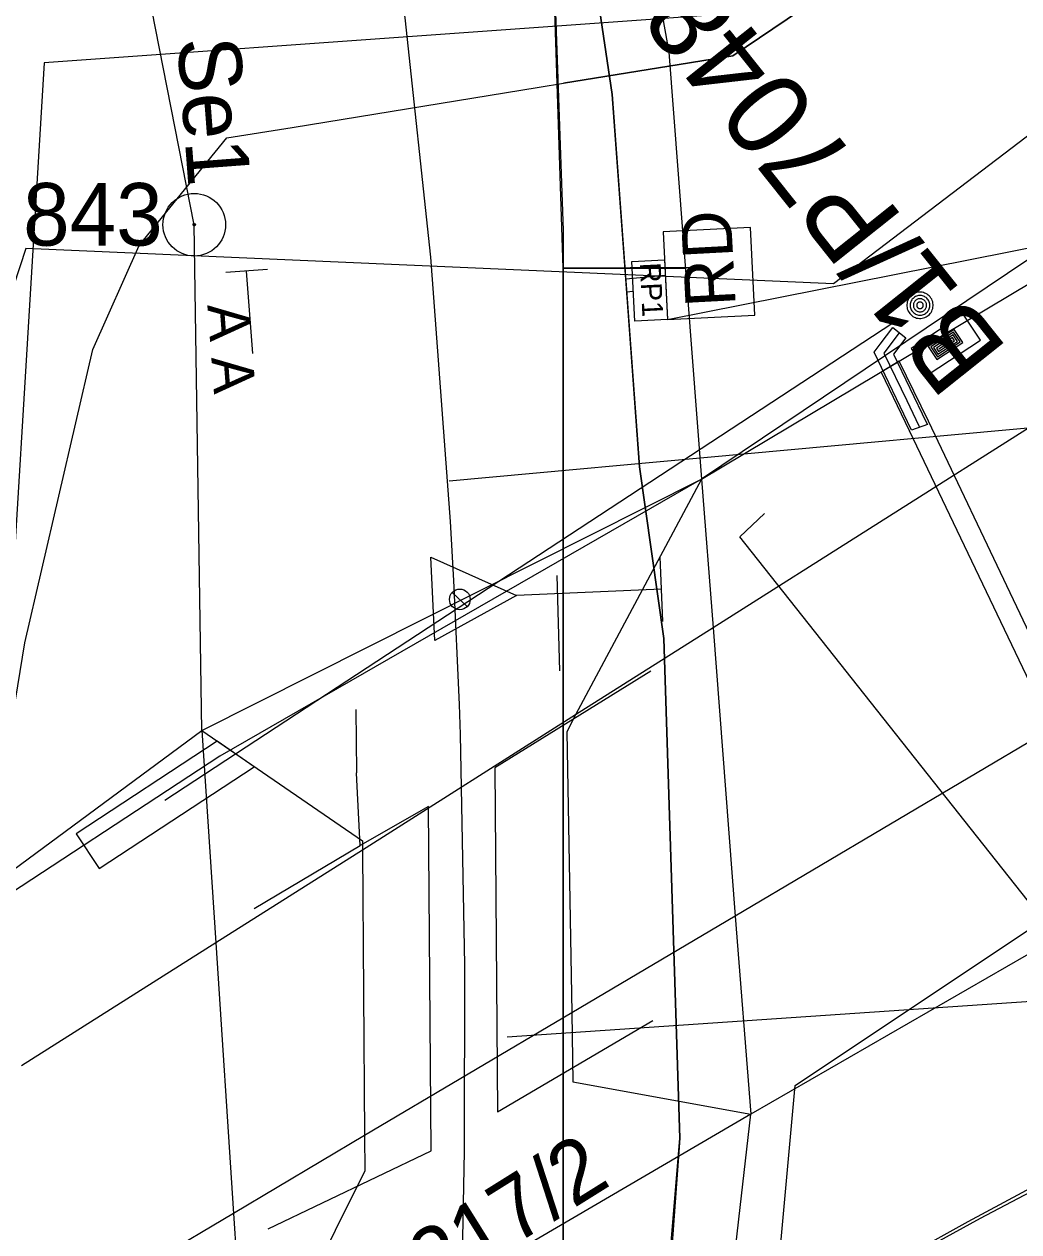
# Model space of a CAD drawing. Extents: x -620475 to -619963, y -1123010 to -1122510.
# Drawn here: x -620144.64 to -620120.79, y -1122910.94 to -1122881.99 of the extents above; entities that cross this region are included whole.
import ezdxf

# ---------------------------------------------------------------- set-up
doc = ezdxf.new("R2010")
doc.units = 0
for name, color, linetype in [('060603_ROZVODY_NN', 7, 'Continuous'), ('bubliny', 7, 'Continuous'), ('CD-T  SDK', 7, 'Continuous'), ('CETIN', 7, 'Continuous'), ('EON-nadzemní NN', 7, 'Continuous'), ('EON-podzemní NN', 7, 'Continuous'), ('HranDP', 7, 'Continuous'), ('Hranice parcel', 7, 'Continuous'), ('Město Bystřice-osvětlení', 7, 'Continuous'), ('Parcelní čísla', 7, 'Continuous'), ('PS 06-14-01_trasa_sdělovací_nové', 7, 'Continuous'), ('SSZT', 7, 'Continuous'), ('SSZT-DK', 7, 'Continuous'), ('SSZT-DK SDK', 7, 'Continuous'), ('SSZT-TK', 7, 'Continuous'), ('VAS el kabel', 7, 'Continuous'), ('Vnitřní kresba', 7, 'Continuous'), ('Vrstva 1', 7, 'Continuous'), ('Vrstva 19', 7, 'Continuous'), ('Vrstva 2', 7, 'Continuous'), ('Vrstva 3', 7, 'Continuous'), ('Vrstva 4', 7, 'Continuous'), ('Vrstva 51', 7, 'Continuous'), ('Vrstva 6', 7, 'Continuous'), ('Vrstva 8', 7, 'Continuous'), ('Věcná břemena k části', 7, 'Continuous'), ('Značky bodu BP', 7, 'Continuous'), ('ČD-T', 7, 'Continuous')]:
    doc.layers.add(name, color=color, linetype=linetype)

# ---------------------------------------------------------------- blocks, each defined once
blk = doc.blocks.new('NN460')
at = {"layer": 'Vrstva 2'}
for points in [[(0.628, 0), (0.624, 0.066), (0.614, 0.132), (0.597, 0.195), (0.573, 0.257), (0.543, 0.315), (0.507, 0.371), (0.466, 0.422), (0.419, 0.468), (0.368, 0.51), (0.312, 0.546), (0.254, 0.576), (0.192, 0.6), (0.129, 0.617), (0.063, 0.627), (-0.003, 0.631), (-0.068, 0.627), (-0.133, 0.617), (-0.197, 0.6), (-0.259, 0.576), (-0.317, 0.546), (-0.373, 0.51), (-0.424, 0.468), (-0.471, 0.422), (-0.512, 0.371), (-0.548, 0.315), (-0.578, 0.257), (-0.602, 0.195), (-0.619, 0.132), (-0.629, 0.066), (-0.632, 0), (-0.629, -0.065), (-0.619, -0.131), (-0.602, -0.194), (-0.578, -0.256), (-0.548, -0.315), (-0.512, -0.37), (-0.471, -0.421), (-0.424, -0.468), (-0.373, -0.509), (-0.317, -0.545), (-0.259, -0.575), (-0.197, -0.599), (-0.133, -0.616), (-0.068, -0.626), (-0.003, -0.63), (0.063, -0.626), (0.129, -0.616), (0.192, -0.599), (0.254, -0.575), (0.313, -0.545), (0.368, -0.509), (0.419, -0.468), (0.466, -0.421), (0.507, -0.37), (0.543, -0.315), (0.573, -0.256), (0.597, -0.194), (0.614, -0.131), (0.624, -0.065), (0.628, 0)], [(0.47, 0), (0.467, 0.05), (0.46, 0.099), (0.447, 0.147), (0.429, 0.193), (0.407, 0.237), (0.38, 0.278), (0.349, 0.317), (0.314, 0.352), (0.275, 0.383), (0.234, 0.41), (0.19, 0.432), (0.144, 0.45), (0.096, 0.463), (0.047, 0.47), (-0.003, 0.473), (-0.052, 0.47), (-0.1, 0.463), (-0.148, 0.45), (-0.194, 0.432), (-0.239, 0.41), (-0.28, 0.383), (-0.319, 0.352), (-0.353, 0.317), (-0.385, 0.278), (-0.411, 0.237), (-0.434, 0.193), (-0.452, 0.147), (-0.465, 0.099), (-0.472, 0.05), (-0.475, 0), (-0.472, -0.049), (-0.465, -0.098), (-0.452, -0.146), (-0.434, -0.192), (-0.411, -0.236), (-0.385, -0.277), (-0.353, -0.316), (-0.318, -0.351), (-0.28, -0.382), (-0.239, -0.409), (-0.194, -0.431), (-0.148, -0.449), (-0.1, -0.462), (-0.052, -0.469), (-0.003, -0.472), (0.047, -0.469), (0.096, -0.462), (0.144, -0.449), (0.19, -0.431), (0.234, -0.409), (0.275, -0.382), (0.314, -0.351), (0.349, -0.316), (0.38, -0.277), (0.407, -0.236), (0.429, -0.192), (0.447, -0.146), (0.46, -0.098), (0.467, -0.049), (0.47, 0)], [(0.313, 0), (0.311, 0.033), (0.306, 0.066), (0.297, 0.098), (0.285, 0.129), (0.27, 0.158), (0.252, 0.186), (0.232, 0.211), (0.208, 0.234), (0.183, 0.255), (0.155, 0.273), (0.126, 0.288), (0.095, 0.3), (0.063, 0.309), (0.03, 0.314), (-0.003, 0.315), (-0.035, 0.314), (-0.068, 0.309), (-0.1, 0.3), (-0.13, 0.288), (-0.16, 0.273), (-0.187, 0.255), (-0.213, 0.234), (-0.237, 0.211), (-0.257, 0.186), (-0.275, 0.158), (-0.29, 0.129), (-0.302, 0.098), (-0.31, 0.066), (-0.316, 0.033), (-0.317, 0), (-0.316, -0.033), (-0.31, -0.065), (-0.302, -0.097), (-0.29, -0.128), (-0.275, -0.157), (-0.257, -0.185), (-0.237, -0.21), (-0.213, -0.234), (-0.187, -0.254), (-0.16, -0.272), (-0.13, -0.287), (-0.1, -0.299), (-0.068, -0.308), (-0.035, -0.313), (-0.003, -0.315), (0.03, -0.313), (0.063, -0.308), (0.095, -0.299), (0.126, -0.287), (0.155, -0.272), (0.183, -0.254), (0.208, -0.234), (0.232, -0.21), (0.252, -0.185), (0.27, -0.157), (0.285, -0.128), (0.297, -0.097), (0.306, -0.065), (0.311, -0.032), (0.313, 0)], [(0.155, 0), (0.154, 0.017), (0.152, 0.033), (0.147, 0.049), (0.142, 0.064), (0.134, 0.079), (0.125, 0.093), (0.115, 0.106), (0.103, 0.118), (0.09, 0.128), (0.076, 0.137), (0.062, 0.144), (0.046, 0.15), (0.03, 0.154), (0.014, 0.157), (-0.003, 0.158), (-0.019, 0.157), (-0.035, 0.154), (-0.051, 0.15), (-0.066, 0.144), (-0.081, 0.137), (-0.095, 0.128), (-0.108, 0.118), (-0.119, 0.106), (-0.13, 0.093), (-0.139, 0.079), (-0.146, 0.064), (-0.152, 0.049), (-0.156, 0.033), (-0.159, 0.017), (-0.16, 0), (-0.159, -0.016), (-0.156, -0.032), (-0.152, -0.048), (-0.146, -0.064), (-0.139, -0.078), (-0.13, -0.092), (-0.119, -0.105), (-0.108, -0.117), (-0.095, -0.127), (-0.081, -0.136), (-0.066, -0.143), (-0.051, -0.149), (-0.035, -0.153), (-0.019, -0.156), (-0.003, -0.157), (0.014, -0.156), (0.03, -0.153), (0.046, -0.149), (0.062, -0.143), (0.076, -0.136), (0.09, -0.127), (0.103, -0.117), (0.115, -0.105), (0.125, -0.092), (0.134, -0.078), (0.142, -0.064), (0.147, -0.048), (0.152, -0.032), (0.154, -0.016), (0.155, 0)]]:
    blk.add_lwpolyline(points, dxfattribs=at)
blk = doc.blocks.new('NN620')
at = {"layer": 'Vrstva 8'}
for points in [[(0.752, 0.004), (-0.748, 0.004)], [(-0.748, 0.004), (-0.748, -0.746)], [(0.752, -0.746), (0.752, 0.004)], [(0.368, -0.18), (-0.376, -0.18)], [(-0.376, -0.18), (-0.376, -0.558)], [(0.321, -0.227), (-0.329, -0.227)], [(-0.329, -0.227), (-0.329, -0.51)], [(0.274, -0.274), (-0.281, -0.274)], [(-0.281, -0.274), (-0.281, -0.463)], [(0.274, -0.463), (0.274, -0.274)], [(0.321, -0.51), (0.321, -0.227)], [(0.368, -0.558), (0.368, -0.18)], [(-0.376, -0.558), (0.368, -0.558)], [(-0.329, -0.51), (0.321, -0.51)], [(-0.281, -0.463), (0.274, -0.463)], [(0.227, -0.321), (-0.234, -0.321)], [(-0.234, -0.321), (-0.234, -0.416)], [(-0.234, -0.416), (0.227, -0.416)], [(-0.193, -0.369), (0.185, -0.369)], [(0.227, -0.416), (0.227, -0.321)], [(-0.748, -0.746), (0.752, -0.746)]]:
    blk.add_lwpolyline(points, dxfattribs=at)

msp = doc.modelspace()

# ---------------------------------------------------------------- linework, layer by layer
at = {"layer": '060603_ROZVODY_NN'}
msp.add_lwpolyline([(-620240.174, -1122718.342), (-620228.339, -1122728.069), (-620221.166, -1122735.76), (-620213.633, -1122742.038), (-620205.954, -1122748.188), (-620177.512, -1122774.524), (-620185.522, -1122781.049), (-620181.59, -1122785.57), (-620173.131, -1122796.401), (-620158.909, -1122820.61), (-620151.64, -1122838.53), (-620148.846, -1122845.743), (-620146.967, -1122851.788), (-620142.651, -1122873.562), (-620132.315, -1122871.722), (-620130.544, -1122883.681), (-620130.195, -1122888.406), (-620130.037, -1122888.394)], dxfattribs=at)
msp.add_lwpolyline([(-620129.287, -1122887.643), (-620129.216, -1122889.068), (-620130.001, -1122889.107), (-620130.072, -1122887.682)], close=True, dxfattribs=at)
at = {"layer": 'bubliny'}
msp.add_line((-620129.216, -1122889.068), (-620082.81, -1122879.869), dxfattribs=at)
at = {"layer": 'CD-T  SDK'}
msp.add_lwpolyline([(-620105.449, -1122868.581), (-620124.482, -1122881.511), (-620144.155, -1122882.921), (-620145.292, -1122901.532), (-620189.847, -1122929.066)], dxfattribs=at)
at = {"layer": 'CETIN'}
for points in [[(-620127.251, -1122919.476), (-620126.15, -1122907.427), (-620051.64, -1122857.73)], [(-620170.67, -1122919.52), (-620165.17, -1122915.89), (-620159.81, -1122912.93), (-620154.47, -1122909.86), (-620149, -1122906.77), (-620145.47, -1122904.13), (-620145.58, -1122902.66), (-620144.62, -1122896.82), (-620142.99, -1122889.79), (-620141.88, -1122887.3), (-620139.78, -1122884.72), (-620138.21, -1122884.47), (-620132.29, -1122883.5), (-620131.71, -1122883.41), (-620127.65, -1122882.75), (-620121.18, -1122878.38), (-620115.35, -1122873.32), (-620112.07, -1122871.4), (-620109.58, -1122869.93), (-620106.94, -1122868.3), (-620100.13, -1122864.1), (-620091.57, -1122858.83)], [(-620100.13, -1122864.1), (-620106.94, -1122868.3), (-620109.58, -1122869.93), (-620112.07, -1122871.4), (-620115.35, -1122873.32), (-620121.18, -1122878.38), (-620127.65, -1122882.75), (-620131.71, -1122883.41)], [(-620138.21, -1122884.47), (-620132.29, -1122883.5)]]:
    msp.add_lwpolyline(points, dxfattribs=at)
at = {"layer": 'EON-nadzemní NN'}
msp.add_lwpolyline([(-620123.81, -1122889.156), (-620141.262, -1122900.597)], dxfattribs=at)
at = {"layer": 'EON-podzemní NN'}
msp.add_lwpolyline([(-620123.816, -1122889.266), (-620123.497, -1122889.507), (-620123.797, -1122889.903), (-620123.01, -1122891.533), (-620122.985, -1122891.585), (-620123.363, -1122891.722), (-620123.37, -1122891.707), (-620124.263, -1122889.857), (-620124.116, -1122889.662)], close=True, dxfattribs=at)
msp.add_lwpolyline([(-620123.657, -1122889.387), (-620124.03, -1122889.88), (-620123.48, -1122891.01), (-620123.19, -1122891.62), (-620123.174, -1122891.654)], dxfattribs=at)
at = {"layer": 'HranDP'}
for points in [[(-620143.18, -1122816.17), (-620134.66, -1122852.11), (-620129.18, -1122882.66), (-620128.4, -1122892.9)], [(-620140.38, -1122898.92), (-620140.56, -1122886.8), (-620147.76, -1122850.22), (-620152.84, -1122837.4)], [(-620128.4, -1122892.9), (-620131.42, -1122898.55), (-620131.63, -1122898.95), (-620131.51, -1122905.69)], [(-620140.38, -1122898.92), (-620136.53, -1122901.57), (-620136.53, -1122901.79), (-620136.48, -1122908.63), (-620136.47, -1122909.48), (-620139.31, -1122915.18)], [(-620131.51, -1122905.69), (-620131.48, -1122907.34), (-620127.22, -1122908.12)], [(-620139.01, -1122969.61), (-620134.15, -1122956.58), (-620131.17, -1122942.74), (-620127.22, -1122908.12)]]:
    msp.add_lwpolyline(points, dxfattribs=at)
at = {"layer": 'Hranice parcel'}
for p, q in [((-620140.38, -1122898.92), (-620128.4, -1122892.9)), ((-620105.32, -1122895.5), (-620127.22, -1122908.12)), ((-620146.13, -1122903.17), (-620140.38, -1122898.92)), ((-620127.22, -1122908.12), (-620139.31, -1122915.18))]:
    msp.add_line(p, q, dxfattribs=at)
for points in [[(-620143.18, -1122816.17), (-620134.66, -1122852.11), (-620129.18, -1122882.66), (-620128.4, -1122892.9)], [(-620140.38, -1122898.92), (-620140.56, -1122886.8), (-620147.76, -1122850.22), (-620152.84, -1122837.4)], [(-620128.4, -1122892.9), (-620078.79, -1122863.28), (-620080.86, -1122856.55)], [(-620128.4, -1122892.9), (-620131.42, -1122898.55), (-620131.63, -1122898.95), (-620131.51, -1122905.69)], [(-620140.38, -1122898.92), (-620136.53, -1122901.57), (-620136.53, -1122901.79), (-620136.48, -1122908.63), (-620136.47, -1122909.48), (-620139.31, -1122915.18)], [(-620131.51, -1122905.69), (-620131.48, -1122907.34), (-620127.22, -1122908.12)], [(-620139.01, -1122969.61), (-620134.15, -1122956.58), (-620131.17, -1122942.74), (-620127.22, -1122908.12)]]:
    msp.add_lwpolyline(points, dxfattribs=at)
at = {"layer": 'Město Bystřice-osvětlení'}
msp.add_lwpolyline([(-620092.297, -1122836.326), (-620103.44, -1122876.118), (-620128.4, -1122892.9), (-620139.95, -1122899.534), (-620145.972, -1122903.483), (-620174.136, -1122920.728), (-620208.83, -1122942.099)], dxfattribs=at)
at = {"layer": 'PS 06-14-01_trasa_sdělovací_nové'}
msp.add_lwpolyline([(-620158.909, -1122820.61), (-620151.64, -1122838.53), (-620148.846, -1122845.743), (-620147.082, -1122852.395), (-620142.651, -1122873.562), (-620132.315, -1122871.722), (-620130.544, -1122883.681), (-620129.885, -1122892.603), (-620129.304, -1122896.718), (-620128.917, -1122908.694), (-620129.363, -1122914.829), (-620129.689, -1122921.326), (-620138.779, -1122920.925), (-620145.54, -1122954.13), (-620150.629, -1122971.371), (-620142.936, -1122974.459), (-620142.936, -1122974.459)], dxfattribs=at)
at = {"layer": 'SSZT'}
for points in [[(-620131.713, -1122887.843), (-620132.103, -1122876.02), (-620140.705, -1122844.513), (-620144.18, -1122829.908), (-620149.89, -1122817.622), (-620160.216, -1122801.593), (-620175.654, -1122778.856), (-620179.825, -1122771.902), (-620189.291, -1122760.708), (-620207.424, -1122744.252), (-620237.066, -1122720.469), (-620255.602, -1122705.516), (-620251.355, -1122700.201)], [(-620131.713, -1122914.315), (-620131.713, -1122887.843), (-620128.763, -1122887.843)]]:
    msp.add_lwpolyline(points, dxfattribs=at)
at = {"layer": 'SSZT-DK'}
msp.add_lwpolyline([(-620110.298, -1122902.137), (-620109.5, -1122903.979), (-620122.012, -1122910.698), (-620123.234, -1122911.378), (-620124.411, -1122912.619), (-620125.127, -1122913.842), (-620126.05, -1122915.989), (-620127.097, -1122919.362), (-620128.151, -1122923.579), (-620130.396, -1122942.577), (-620131.915, -1122949.61), (-620133.435, -1122956.642), (-620137.096, -1122967.179), (-620142.132, -1122981.675), (-620149.093, -1122999.398)], dxfattribs=at)
at = {"layer": 'SSZT-DK SDK'}
msp.add_lwpolyline([(-620098.563, -1122867.909), (-620125.234, -1122888.212), (-620144.595, -1122887.369), (-620150.227, -1122904.525), (-620151.977, -1122908.188), (-620181.024, -1122925.755)], dxfattribs=at)
at = {"layer": 'SSZT-TK'}
msp.add_lwpolyline([(-620251.547, -1122700.3), (-620255.602, -1122705.516), (-620237.066, -1122720.469), (-620207.424, -1122744.252), (-620189.291, -1122760.708), (-620179.825, -1122771.902), (-620175.654, -1122778.856), (-620160.216, -1122801.593), (-620149.89, -1122817.622), (-620144.18, -1122829.908), (-620140.705, -1122844.513), (-620132.103, -1122876.02), (-620131.713, -1122886.934), (-620131.713, -1122887.843), (-620128.502, -1122887.822), (-620131.713, -1122887.843), (-620131.713, -1122914.315), (-620136.813, -1122914.315), (-620139.347, -1122912.91)], dxfattribs=at)
at = {"layer": 'VAS el kabel'}
msp.add_lwpolyline([(-620136.001, -1122984.432), (-620126.051, -1122955.588), (-620113.383, -1122918.863), (-620112.629, -1122916.423), (-620111.874, -1122913.983), (-620119.677, -1122904.131), (-620127.479, -1122894.28), (-620127.184, -1122894), (-620126.89, -1122893.72)], dxfattribs=at)
at = {"layer": 'Vnitřní kresba'}
for p, q in [((-620119.37, -1122890.92), (-620128.12, -1122896.46)), ((-620128.4, -1122892.9), (-620128.12, -1122896.46)), ((-620115.07, -1122895.95), (-620127.59, -1122903.37)), ((-620128.12, -1122896.46), (-620131.42, -1122898.55)), ((-620128.12, -1122896.46), (-620127.59, -1122903.37)), ((-620131.42, -1122898.55), (-620136.53, -1122901.79)), ((-620140.38, -1122898.92), (-620140.04, -1122904.01)), ((-620136.53, -1122901.79), (-620140.04, -1122904.01)), ((-620127.59, -1122903.37), (-620131.51, -1122905.69)), ((-620127.59, -1122903.37), (-620127.22, -1122908.12)), ((-620140.04, -1122904.01), (-620144.7, -1122906.96)), ((-620140.04, -1122904.01), (-620139.62, -1122910.5)), ((-620131.51, -1122905.69), (-620136.48, -1122908.63)), ((-620136.48, -1122908.63), (-620139.62, -1122910.5)), ((-620139.62, -1122910.5), (-620141.9, -1122911.85)), ((-620139.62, -1122910.5), (-620139.31, -1122915.18))]:
    msp.add_line(p, q, dxfattribs=at)
at = {"layer": 'Vrstva 1'}
for p, q in [((-620129.268, -1122888.018), (-620130.217, -1122888.107)), ((-620128.917, -1122908.694), (-620129.304, -1122896.718))]:
    msp.add_line(p, q, dxfattribs=at)
for points in [[(-620149.889, -1122827.962), (-620146.963, -1122835.3), (-620144.335, -1122842.644), (-620141.899, -1122850.478), (-620139.852, -1122858.172), (-620138.087, -1122866.061), (-620136.624, -1122873.963), (-620135.508, -1122881.838), (-620134.899, -1122887.574), (-620134.421, -1122893.912), (-620134.342, -1122895.324), (-620134.207, -1122898.299), (-620134.183, -1122899.017), (-620134.083, -1122904.541), (-620134.086, -1122909.002), (-620134.143, -1122911.917), (-620134.478, -1122918.719), (-620135.164, -1122926.756), (-620136.29, -1122935.458), (-620137.6, -1122943.19), (-620139.253, -1122951.105)], [(-620130.217, -1122888.107), (-620130.544, -1122883.681), (-620132.315, -1122871.722), (-620133.37, -1122871.922)], [(-620129.304, -1122896.718), (-620129.885, -1122892.603), (-620129.885, -1122892.603), (-620130.217, -1122888.107)], [(-620129.469, -1122916.939), (-620129.257, -1122912.719), (-620129.257, -1122912.719), (-620128.917, -1122908.694)]]:
    msp.add_lwpolyline(points, dxfattribs=at)
at = {"layer": 'Vrstva 19'}
for p, q in [((-620074.697, -1122887.466), (-620134.446, -1122892.947)), ((-620131.869, -1122895.208), (-620131.802, -1122897.494))]:
    msp.add_line(p, q, dxfattribs=at)
msp.add_lwpolyline([(-620139.122, -1122903.19), (-620136.585, -1122901.678), (-620136.672, -1122899.948), (-620136.66, -1122899.922), (-620136.676, -1122898.417)], dxfattribs=at)
at = {"layer": 'Vrstva 2'}
msp.add_lwpolyline([(-620127.12, -1122888.964), (-620127.225, -1122886.864), (-620129.32, -1122886.969), (-620129.216, -1122889.068)], close=True, dxfattribs=at)
at = {"layer": 'Vrstva 4'}
for p, q in [((-620129.327, -1122896.311), (-620129.391, -1122894.757)), ((-620134.015, -1122895.946), (-620134.374, -1122895.613)), ((-620133.061, -1122906.266), (-620073.199, -1122902.2))]:
    msp.add_line(p, q, dxfattribs=at)
for points in [[(-620129.359, -1122895.534), (-620132.833, -1122895.689), (-620134.793, -1122896.764), (-620134.887, -1122894.768), (-620132.833, -1122895.689)], [(-620134.183, -1122899.017), (-620134.083, -1122904.541), (-620134.086, -1122909.002)]]:
    msp.add_lwpolyline(points, dxfattribs=at)
msp.add_circle((-620134.193, -1122895.78), 0.248, dxfattribs=at)
at = {"layer": 'Vrstva 51'}
for points in [[(-620129.616, -1122897.497), (-620133.356, -1122899.815), (-620133.289, -1122908.064), (-620129.566, -1122905.874)], [(-620138.786, -1122910.866), (-620134.879, -1122908.999), (-620134.943, -1122900.747), (-620136.585, -1122901.678)]]:
    msp.add_lwpolyline(points, dxfattribs=at)
at = {"layer": 'Vrstva 6'}
for p, q in [((-620138.807, -1122887.871), (-620139.805, -1122887.947)), ((-620139.157, -1122889.883), (-620139.306, -1122887.909))]:
    msp.add_line(p, q, dxfattribs=at)
at = {"layer": 'Věcná břemena k části'}
for points in [[(-620116.97, -1122902.21), (-620118.88, -1122900.07), (-620122.96, -1122891.51), (-620123.66, -1122890.07), (-620124.09, -1122890.33), (-620123.42, -1122891.73), (-620119.3, -1122900.35), (-620117.41, -1122902.47)], [(-620139.12, -1122899.79), (-620140.01, -1122899.18), (-620143.39, -1122901.4), (-620142.84, -1122902.23)]]:
    msp.add_lwpolyline(points, close=True, dxfattribs=at)
at = {"layer": 'Značky bodu BP'}
for radius in [0.75, 0.03]:
    msp.add_circle((-620140.56, -1122886.8), radius, dxfattribs=at)
at = {"layer": 'ČD-T'}
msp.add_lwpolyline([(-620110.11, -1122901.903), (-620109.165, -1122904.011), (-620121.715, -1122910.619), (-620123.191, -1122911.428), (-620124.347, -1122912.673), (-620125.054, -1122913.872), (-620125.863, -1122915.755), (-620126.91, -1122919.128), (-620127.963, -1122923.345), (-620130.209, -1122942.343), (-620131.728, -1122949.375), (-620133.248, -1122956.408), (-620136.909, -1122966.945), (-620141.945, -1122981.441), (-620148.92, -1122999.201)], dxfattribs=at)

# ---------------------------------------------------------------- block references
at = {"layer": 'EON-podzemní NN', "xscale": 0.5, "yscale": 0.5, "rotation": 33.24746664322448}
msp.add_blockref('NN460', (-620123.16, -1122888.73), dxfattribs=at)
at = {"layer": 'EON-podzemní NN', "rotation": 33.24700008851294}
msp.add_blockref('NN620', (-620122.749, -1122889.358), dxfattribs=at)

# ---------------------------------------------------------------- texts
at = {"layer": '060603_ROZVODY_NN'}
msp.add_text('RP1', height=0.5, rotation=272.8435, dxfattribs=at).set_placement((-620129.879, -1122887.718))
at = {"layer": 'Parcelní čísla'}
msp.add_text('3217/2', height=1.5, rotation=32, dxfattribs=at).set_placement((-620135.731, -1122913.045))
at = {"layer": 'Vrstva 2'}
msp.add_text('RD', height=1.2, rotation=93.0505, dxfattribs=at).set_placement((-620127.578, -1122888.74))
at = {"layer": 'Vrstva 3'}
msp.add_text('B1/P7048', height=2, rotation=128.542, dxfattribs=at).set_placement((-620121.024, -1122889.806))
at = {"layer": 'Vrstva 6'}
for s, height, p in [('Se1', 1.5, (-620140.967, -1122882.35)), ('  A A ', 1, (-620140.303, -1122887.984))]:
    msp.add_text(s, height=height, rotation=274.313, dxfattribs=at).set_placement(p)
at = {"layer": 'Značky bodu BP'}
msp.add_text('843', height=1.5, dxfattribs=at).set_placement((-620144.663, -1122887.3))

doc.saveas('drawing.dxf')
